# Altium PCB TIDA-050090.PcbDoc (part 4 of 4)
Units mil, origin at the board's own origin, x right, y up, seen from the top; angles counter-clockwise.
Board outline 4150 x 4140 mil, 8 copper layers (Top Layer 1, POWER1, GND1, SIGNAL1, SIGNAL2, GND2, POWER2, Bottom Layer 1), stack 60.703 mil thick; 130 components, 39 nets, 355 pads, 2292 vias.
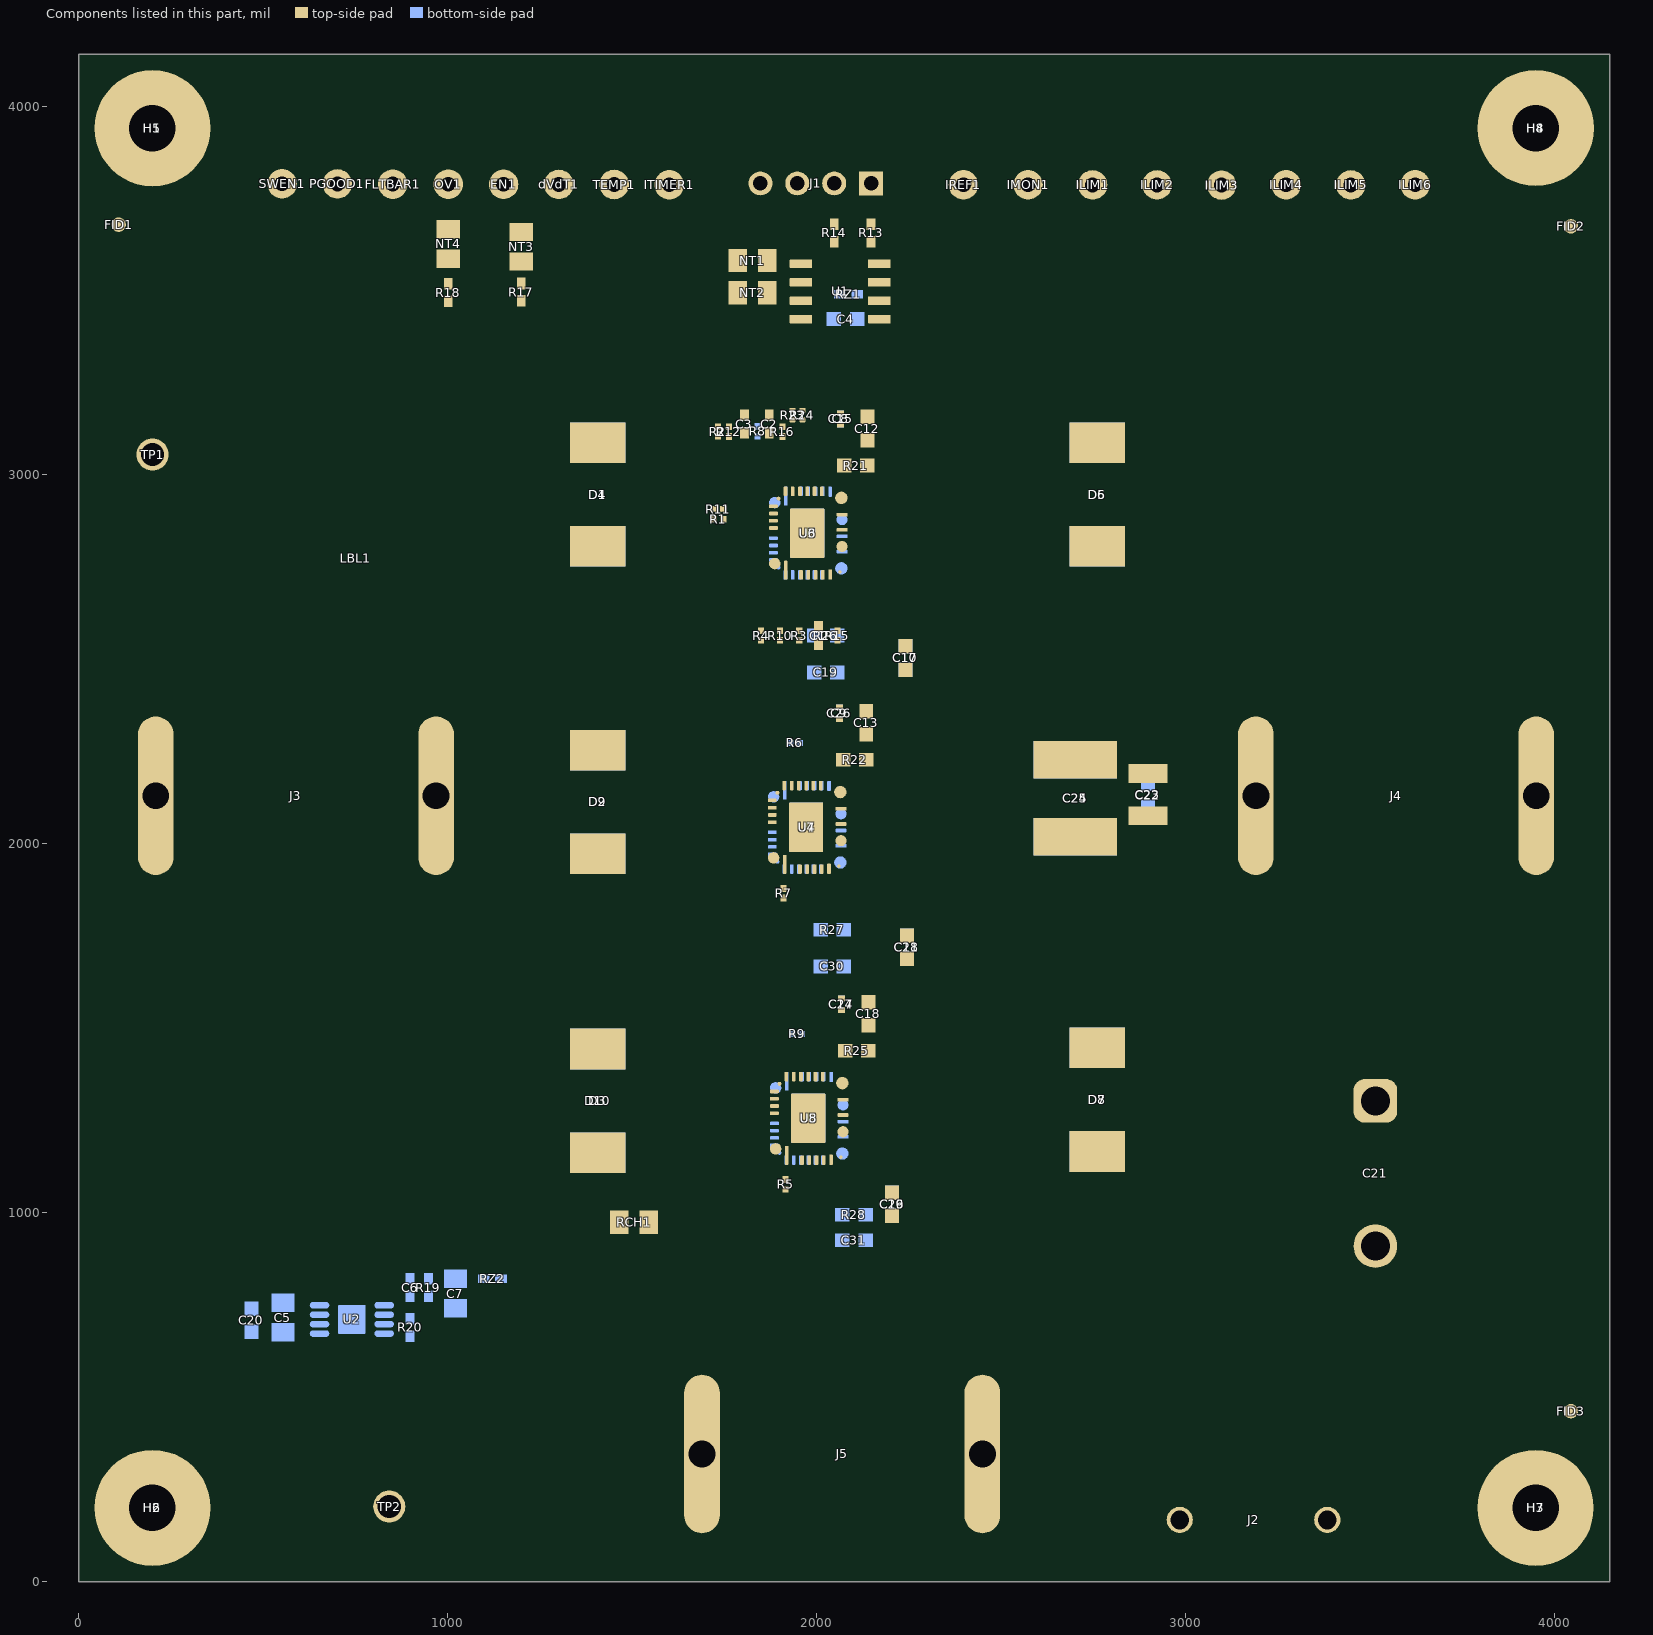
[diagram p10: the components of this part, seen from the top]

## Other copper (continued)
Bottom Layer 1:
  pour cut-out: 172.94,3678.58 ccw(c127.94,3678.58) 127.94,3723.58 ccw(c127.94,3678.58) 82.94,3678.58 ccw(c127.94,3678.58) 127.94,3633.58 ccw(c127.94,3678.58)
  pour cut-out: 4070.58,3674.15 ccw(c4025.58,3674.15) 4025.58,3719.15 ccw(c4025.58,3674.15) 3980.58,3674.15 ccw(c4025.58,3674.15) 4025.58,3629.15 ccw(c4025.58,3674.15)
  pour cut-out: 4090.27,482.52 ccw(c4045.27,482.52) 4045.27,527.52 ccw(c4045.27,482.52) 4000.27,482.52 ccw(c4045.27,482.52) 4045.27,437.52 ccw(c4045.27,482.52)
  region net QGND1: 2218.4,2492.36 2209.85,2483.81 2209.85,2428.49 2216.7,2421.65 2268.53,2421.65 2275.75,2428.87 2275.75,2485.14 2268.53,2492.36
  region net QGND1: 2222.34,1708.21 2213.79,1699.66 2213.79,1644.34 2220.64,1637.5 2272.47,1637.5 2279.69,1644.72 2279.69,1700.99 2272.47,1708.21
  region net PGND: 1486.21,3025.82 1328.73,3025.82 1318.89,3035.67 1318.89,3218.93 1342.31,3242.36 1476.37,3242.36 1496.05,3222.68 1496.05,3035.67
  region net PGND: 1486.21,2192.64 1328.73,2192.64 1318.89,2202.48 1318.89,2385.75 1342.31,2409.17 1476.37,2409.17 1496.05,2389.49 1496.05,2202.48
  region net PGND: 2840.3,3025.82 2682.82,3025.82 2672.97,3035.67 2672.97,3218.93 2696.4,3242.36 2830.45,3242.36 2850.14,3222.68 2850.14,3035.67
  region net PGND: 2682.8,1227.81 2840.28,1227.81 2850.13,1217.97 2850.13,1034.7 2826.7,1011.28 2692.65,1011.28 2672.96,1030.96 2672.96,1217.97
  region net PGND: 1318.89,948.42 1367.47,899.84 1481.58,899.84 1496.05,914.31 1496.05,1214.8 1486.21,1224.64 1328.73,1224.64 1318.89,1214.8
  region net PGND: 2603.36,2342.6 2603.36,2179.37 2639.36,2143.36 2947.85,2143.36 2951.82,2147.34 2951.82,2329.5 2921.02,2360.31 2621.07,2360.31
  region net PGND: 444.44,700.51 430.28,686.36 430.28,585.35 442.56,573.07 583.69,573.07 596.82,586.19 596.82,691.94 588.24,700.51
  region net PGND: 975.43,681.34 984.59,690.5 984.59,760.56 989.94,765.92 1060.29,765.92 1066.13,760.08 1066.13,602.6 1060.91,597.38 1023.75,597.38 839.95,597.38 796.92,640.41 729.34,640.41 698.94,670.81 698.94,754.71 702.93,758.7 778.74,758.7 784.45,753 784.45,698.51 801.62,681.34
  region net Efuse_OUT: 2682.82,2868.34 2840.3,2868.34 2850.14,2858.5 2850.14,2675.23 2826.71,2651.81 2692.66,2651.81 2672.97,2671.49 2672.97,2858.5
  region net Efuse_OUT: 2840.28,1385.3 2682.8,1385.3 2672.96,1395.14 2672.96,1578.41 2696.39,1601.83 2830.44,1601.83 2850.13,1582.15 2850.13,1395.14
  region net Efuse_OUT: 2121.52,2528.31 2135.82,2514.01 2196.23,2514.01 2196.43,2514.21 2392.29,2514.21 2392.49,2514.01 2411.41,2532.93 2411.41,2956.93 2391.72,2976.61 2201.03,2976.61 2138.22,2913.8 2052.94,2913.8 2050.25,2911.1 2050.24,2906.06 2050.24,2819.27 2059.85,2809.29 2091.74,2809.29 2121.52,2779.51
  region net Efuse_OUT: 2945.47,2121 2675.28,2121 2591.55,2037.27 2591.55,1902.38 2609.83,1884.09 2905.11,1884.09 2974.01,1952.99 2974.01,2092.47
  region net Efuse_OUT: 2170.34,1144.42 2170.34,1035.95 2178.5,1027.79 2404.18,1027.79 2414.02,1037.64 2414.02,1370.48 2394.34,1390.17 2203.65,1390.17 2140.84,1327.36 2055.56,1327.36 2052.86,1324.66 2052.86,1319.62 2052.86,1232.83 2062.47,1222.85 2091.92,1222.85
  region net Efuse_OUT: 2118.58,1730.81 2132.88,1716.51 2193.29,1716.51 2193.49,1716.71 2389.36,1716.71 2389.56,1716.51 2408.47,1735.43 2408.47,2159.43 2388.79,2179.11 2198.1,2179.11 2135.29,2116.3 2050.01,2116.3 2047.31,2113.6 2047.31,2108.56 2047.31,2021.77 2056.91,2011.79 2088.8,2011.79 2118.58,1982.01
  region net Efuse_OUT: 3163.01,2425.04 3131.61,2393.64 3131.61,1868.39 3157.95,1842.05 4033.05,1842.05 4045.18,1854.17 4045.18,2405.35 4025.49,2425.04
  region net Efuse_IN: 1328.73,2868.34 1486.21,2868.34 1496.05,2858.5 1496.05,2675.23 1472.63,2651.81 1338.57,2651.81 1318.89,2671.49 1318.89,2858.5
  region net Efuse_IN: 1328.73,2035.16 1486.21,2035.16 1496.05,2025.31 1496.05,1842.05 1472.63,1818.62 1338.57,1818.62 1318.89,1838.31 1318.89,2025.31
  region net Efuse_IN: 1486.21,1382.12 1328.73,1382.12 1318.89,1391.97 1318.89,1575.23 1342.31,1598.66 1476.37,1598.66 1496.05,1578.97 1496.05,1391.97
  region net Efuse_IN: 1784.51,2815.31 1784.51,2921.18 1793.67,2930.33 1834.41,2930.33 1847.4,2917.35 1847.4,2881.89 1858.25,2871.04 1889.26,2871.04 1903.15,2857.15 1903.15,2782.46 1914.68,2770.93 2019.34,2770.93 2022.6,2774.19 2022.6,2919.57 2007.15,2935.02 1945.58,2935.02 1930.71,2949.89 1930.71,2981.52 1908.02,3004.2 1714.97,3004.17 1692.9,2982.1 1692.9,2829.57 1651.04,2787.7 1651.04,2680.12 1670.92,2660.24 1836.45,2660.24 1843.18,2666.98 1843.18,2756.64
  region net Efuse_IN: 1958.04,1338.73 1933.32,1363.45 1933.32,1395.07 1910.64,1417.76 1717.59,1417.73 1705.36,1405.5 1705.36,1252.97 1653.65,1201.26 1653.65,1093.68 1673.53,1073.8 1839.06,1073.8 1845.8,1080.53 1845.8,1170.19 1796.6,1219.39 1796.6,1274.36 1806.84,1284.6 1891.87,1284.6 1905.76,1270.71 1905.76,1196.02 1917.3,1184.49 2021.95,1184.49 2025.22,1187.75 2025.22,1321.45 2007.93,1338.73
  region net Efuse_IN: 1952.49,2127.68 1927.77,2152.39 1927.77,2184.02 1905.09,2206.7 1712.04,2206.67 1699.81,2194.45 1699.81,2041.91 1648.1,1990.2 1648.1,1882.62 1667.98,1862.74 1833.51,1862.74 1840.25,1869.48 1840.25,1959.14 1791.05,2008.34 1791.05,2063.31 1801.28,2073.54 1886.32,2073.54 1900.21,2059.65 1900.21,1984.96 1911.74,1973.43 2016.4,1973.43 2019.67,1976.69 2019.66,2110.39 2002.38,2127.68
  region net Efuse_IN: 444.44,716.85 430.28,731.01 430.28,841.53 441.93,853.19 585.03,853.19 596.82,841.4 596.82,725.43 588.24,716.85
  region net Efuse_IN: 190.85,2419.05 155.94,2384.14 155.94,1882.95 196.84,1842.05 1050.86,1842.05 1062.98,1854.17 1062.98,2405.35 1049.29,2419.05
  text ".Layer_Name" at 572.49,-1004.76 h60

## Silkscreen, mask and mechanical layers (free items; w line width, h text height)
Top Overlay:
  lines w5: 1907.91,3149.76 1907.91,3208.74
  lines w10: 1702.76,935.04 1702.76,885.04 1739.97,885.04 ; 1702.76,981.2 1702.76,1018.41 ; 1702.76,1055.25 1702.76,1092.47 ; 1702.76,1129.3 1702.76,1166.52 ; 1702.76,1203.35 1702.76,1240.57 ; 1702.76,1277.4 1702.76,1314.62 ; 1702.76,1351.45 1702.76,1388.67 ; 1702.76,1425.5 1702.76,1462.72 ; 1702.76,1499.55 1702.76,1536.77 ; 1702.76,1573.6 1702.76,1610.82 ; 1702.76,1647.65 1702.76,1684.87 ; 1702.76,1721.7 1702.76,1758.92 ; 1702.76,1795.76 1702.76,1832.97 ; 1702.76,1869.81 1702.76,1907.02 ; 1702.76,1943.86 1702.76,1981.08 ; 1702.76,2017.91 1702.76,2055.13 ; 1702.76,2091.96 1702.76,2129.18 ; 1702.76,2166.01 1702.76,2203.23 ; 1702.76,2240.06 1702.76,2277.28 ; 1702.76,2314.11 1702.76,2351.33 ; 1702.76,2388.16 1702.76,2425.38 ; 1702.76,2462.21 1702.76,2499.43 ; 1702.76,2536.26 1702.76,2573.48 ; 1702.76,2610.31 1702.76,2647.53 ; 1702.76,2684.37 1702.76,2721.58 ; 1702.76,2758.42 1702.76,2832.47 ; 1702.76,2943.74 1702.76,3017.79 ; 1702.76,3054.62 1702.76,3091.84 ; 1702.76,3128.67 1702.76,3165.89 ; 1702.76,3202.72 1702.76,3276.77 1739.97,3276.77 ; 1776.81,885.04 1814.03,885.04 ; 1776.81,3276.77 1814.02,3276.77 ; 1850.86,885.04 1888.08,885.04 ; 1850.86,3276.77 1888.08,3276.77 ; 1924.91,885.04 1962.13,885.04 ; 1924.91,3276.77 1962.13,3276.77 ; 1998.96,885.04 2036.18,885.04 ; 1998.96,3276.77 2036.18,3276.77 ; 2073.01,885.04 2110.23,885.04 ; 2073.01,3276.77 2110.23,3276.77 ; 2147.06,885.04 2184.28,885.04 ; 2147.06,3276.77 2184.28,3276.77 ; 2221.11,885.04 2258.33,885.04 ; 2221.11,3276.77 2258.33,3276.77 ; 2295.16,885.04 2332.38,885.04 2332.38,935.04 ; 2295.16,3276.77 2332.38,3276.77 2332.38,3202.72 ; 2332.38,981.2 2332.38,1018.41 ; 2332.38,1055.25 2332.38,1092.47 ; 2332.38,1129.3 2332.38,1166.52 ; 2332.38,1203.35 2332.38,1240.57 ; 2332.38,1277.4 2332.38,1314.62 ; 2332.38,1351.45 2332.38,1388.67 ; 2332.38,1425.5 2332.38,1462.72 ; 2332.38,1499.55 2332.38,1536.77 ; 2332.38,1573.6 2332.38,1610.82 ; 2332.38,1647.65 2332.38,1684.87 ; 2332.38,1721.7 2332.38,1758.92 ; 2332.38,1795.76 2332.38,1832.97 ; 2332.38,1869.81 2332.38,1907.02 ; 2332.38,1943.86 2332.38,1981.08 ; 2332.38,2017.91 2332.38,2055.13 ; 2332.38,2091.96 2332.38,2129.18 ; 2332.38,2166.01 2332.38,2203.23 ; 2332.38,2240.06 2332.38,2277.28 ; 2332.38,2314.11 2332.38,2351.33 ; 2332.38,2388.16 2332.38,2425.38 ; 2332.38,2462.21 2332.38,2499.43 ; 2332.38,2536.26 2332.38,2573.48 ; 2332.38,2610.31 2332.38,2647.53 ; 2332.38,2684.37 2332.38,2721.58 ; 2332.38,2758.42 2332.38,2795.63 ; 2332.38,2832.47 2332.38,2869.68 ; 2332.38,2906.52 2332.38,2943.74 ; 2332.38,2980.57 2332.38,3017.79 ; 2332.38,3054.62 2332.38,3091.84 ; 2332.38,3128.67 2332.38,3165.89
  text "GND" at 1865.07,3877.28 h35 r90
  text "FLTB" at 1967.6,3877.28 h35 r90
  text "SCL" at 2061.35,3877.28 h35 r90
  text "SDA" at 2170.2,3873.11 h35 r90
  text "VIN" at 152.63,3158.78 h35
  text "Contact may cause burns" at 2635.42,2534.55 h100
  text "Do not touch!" at 2639.34,2441.43 h100
  text "TPS1689/5_5KW_Solution" at 119.1,1673.23 h60
  text "Contact may cause burns" at 107.22,1091.74 h100
  text "Do not touch!" at 108.27,986.4 h100
  text "PGND" at 782.55,320.19 h35
  text ".Layer_Name" at 572.49,-1004.76 h60
Bottom Overlay:
  drawing of 115 lines, arcs and shapes, not listed
  text "305-PD-24-0471" at 3675.41,367.65 h50
  text "AUG 2024" at 3645.02,280.09 h50
  text ".Layer_Name" at 572.49,-1004.76 h60
Top Paste:
  text ".Layer_Name" at 572.49,-1004.76 h60
Bottom Paste:
  text ".Layer_Name" at 572.49,-1004.76 h60
Top Solder:
  text ".Layer_Name" at 572.49,-1004.76 h60
  text ".Layer_Name" at 572.49,-1004.76 h60
Bottom Solder:
  text ".Layer_Name" at 572.49,-1004.76 h60
Drill Guide:
  text ".Layer_Name" at 572.49,-1004.76 h60
M1 Board Outline:
  the board outline again, w5
  text ".Layer_Name" at 493.75,-1004.76 h60
M2 Board Dimensions:
  rectangle: 120.49,-546.27 495.49,-421.27
  rectangle: -4.51,-421.27 120.49,-296.27
  lines w7: -4.51,-421.27 995.49,-421.27 ; 120.49,-546.27 120.49,-296.27 ; 245.49,-546.27 245.49,-296.27 ; 495.49,-546.27 495.49,-296.27 ; 745.49,-546.27 745.49,-296.27 ; -4.51,-546.27 -4.51,-296.27 995.49,-296.27 995.49,-546.27 -4.51,-546.27
  text ".Layer_Name" at 493.75,-1004.76 h60
M3 3D STEP Top:
  text ".Layer_Name" at 493.75,-1004.76 h60
M4 3D STEP Bottom:
  text ".Layer_Name" at 493.75,-1004.76 h60
M5 Assembly Top:
  lines w10: -316.19,-1076.43 5533.84,-1076.43 ; -316.19,-873.1 5533.84,-873.1 ; -316.19,-669.77 -316.19,-1279.77 3688.81,-1279.77 ; 1259.81,-1279.77 -315.69,-1279.77 -315.69,-669.77 5533.84,-669.77 5533.84,-1279.77 3212.43,-1279.77 ; 1967.7,-1279.77 1967.7,-669.77 ; 2998.48,-873.1 2998.48,-669.77 ; 3720.37,-873.1 3720.37,-669.77 ; 4224.26,-1286.27 4224.26,-1083.43
  text "COMPONENTS MARKED 'DNP' SHOULD NOT BE POPULATED." at 1026.94,-464.77 h60
  text "ASSEMBLY VARIANT:" at 1026.44,-580.27 h60
  text ".VariantName" at 2054.57,-580.27 h60
  text "PCB VIEWED FROM TOP SIDE" at -272.38,-801.93 h60
  text "BOARD #:" at 2011.21,-801.93 h60
  text ".PRJ_Number" at 2470.09,-801.93 h60
  text "REV:" at 3157.11,-801.93 h60
  text ".PCB_Rev" at 3389.56,-801.93 h60
  text "SVN REV:" at 3790.39,-801.93 h60
  text ".VersionControl_RevNumber" at 4284.58,-801.93 h60
  text "TID #:" at 2011.21,-1005.27 h60
  text ".TID" at 2470.09,-1005.27 h60
  text "GENERATED    :" at 2260.06,-1210.13 h60
  text ".Print_Date" at 2983.89,-1210.13 h60
  text ".Print_Time" at 3575.09,-1210.13 h60
  text "PLOT NAME =" at -272.38,-1210.6 h60
  text ".plot_File_Name" at 493.75,-1210.6 h60
  text "TEXAS INSTRUMENTS" at 4395.89,-1210.6 h60
M6 Assembly Bottom:
  lines w10: -316.69,-873.6 5533.84,-873.6 ; -314.69,-1076.93 5533.84,-1076.93 ; 1008.63,-1286.77 1008.63,-1083.93 ; 1551.89,-873.6 1551.89,-670.27 ; 2040.15,-1280.27 5533.84,-1280.27 4075.45,-1280.27 ; 2280.31,-1280.27 -316.69,-1280.27 -316.69,-670.27 5533.84,-670.27 ; 2293.46,-873.6 2293.46,-670.27 ; 3324.24,-1280.27 3324.24,-670.27 ; 5532.84,-1280.27 5532.84,-670.27 ; 5533.34,-1280.27 5533.34,-670.27
  text "COMPONENTS MARKED 'DNP' SHOULD NOT BE POPULATED." at 5699.85,-464.27 h60
  text ".VariantName" at 4360.58,-580.27 h60
  text "ASSEMBLY VARIANT:" at 5360.21,-580.27 h60
  text ".VersionControl_RevNumber" at 1030.99,-802.43 h60
  text "SVN REV:" at 1517.31,-802.43 h60
  text ".PCB_Rev" at 1922.07,-802.43 h60
  text "REV:" at 2162.39,-802.43 h60
  text ".PRJ_Number" at 2762.8,-802.43 h60
  text "BOARD #:" at 3229.56,-802.43 h60
  text "PCB VIEWED FROM BOTTOM SIDE" at 5489.52,-802.43 h60
  text ".TID" at 2782.48,-1005.77 h60
  text "TID #:" at 3229.56,-1005.77 h60
  text "TEXAS INSTRUMENTS" at 840.94,-1211.1 h60
  text ".Print_Time" at 2269.61,-1210.63 h60
  text ".Print_Date" at 2888.37,-1210.63 h60
  text "GENERATED    :" at 3671.26,-1210.63 h60
  text ".plot_File_Name" at 4821.82,-1211.1 h60
  text "PLOT NAME =" at 5489.52,-1211.1 h60
M9 Title Sheet:
  drawing of 54 lines, arcs and shapes, not listed
  text "1" at 656.33,11685.23 h70
  text "2" at 3014.34,11685.23 h70
  text "3" at 5390.99,11685.23 h70
  text "4" at 7766.34,11685.23 h70
  text "A" at -441.01,4295.23 h70
  text "A" at 8853.99,4295.23 h70
  text "B" at -441.01,2419.23 h70
  text "B" at 8853.99,2419.23 h70
  text "C" at -441.01,543.23 h70
  text "C" at 8853.99,543.23 h70
  text "PROJECT TITLE:" at 5818.99,-568.77 h45
  text "TPS1685_5KW_solution" at 5868.99,-702.09 h70
  text "DESIGNED FOR:" at 5818.99,-869.77 h45
  text ".Layer_Name" at 493.75,-1004.76 h60
  text ".PRJ_Customer" at 5868.99,-1009.77 h70
  text "FILE NAME:" at 5818.99,-1169.77 h45
  text ".PCB_File_Name_No_Path" at 5868.99,-1289.77 h50
  text "D" at -441.01,-1328.77 h70
  text "D" at 8853.99,-1328.77 h70
  text "Texas Instruments (TI) and/or its licensors do not warrant the accuracy or completeness of this specification" at 959.49,-1451.6 h45
  text "ENGINEER:" at 5818.99,-1459.77 h45
  text "LAYOUT BY:" at 7323.99,-1459.77 h45
  text "or any information contained therein. TI and/or its licensors do not warrant that this design will meet" at 914.51,-1564.27 h45
  text "Hamza, Hameem" at 5868.99,-1614.76 h70
  text ".PCB_Layout" at 7374.49,-1614.76 h70
  text "the specifications, will be suitable for your application or fit for any particular purpose, or will operate in" at 914.51,-1676.94 h45
  text "ALTIUM DESIGNER VERSION:" at 7323.99,-1769.77 h45
  text "an implementation. TI and/or its licensors do not warrant that the design is production worthy. You should" at 914.51,-1789.6 h45
  text "completely validate and test your design implementation to confirm the system functionality for your application." at 959.49,-1902.27 h40
  text ".print_Scale" at 5868.99,-1903.09 h70
  text ".Application_BuildNumber" at 7374.49,-1903.09 h70
  text "1" at 656.33,-2114.77 h70
  text "2" at 3014.34,-2114.77 h70
  text "3" at 5390.99,-2114.77 h70
  text "4" at 7766.34,-2114.77 h70
M10 Fab Notes:
  drawing of 189 lines, arcs and shapes, not listed
  text "FAB NOTE:" at -222.42,5968.83 h100
  text "1.NO VENDOR LOGO OR NAME ON THE BOARD" at -230.42,5773.44 h80
  text "2.ALL HOLES SHOULD BE FHS." at -230.42,5593.44 h80
  text "3.NEED TO REMOVE THE NON FUNCTIONAL PADS IN INNER LAYERS." at -230.42,5413.44 h80
  text "4.CLIP SILK ON NO MASK AREA." at -230.42,5241.1 h80
  text "5. ALL 7.87 MIL DRILLS SHOULD BE NON-CONDUCTIVE VIA PLUGGING FROM BOTH SIDE." at -230.42,5072.1 h80
  text "DESIGN INFORMATION" at 6855.01,5015.41 h60
  text "MIN. TRACK WIDTH:" at 6210.45,4883.28 h60
  text "10" at 7306.69,4883.29 h60
  text "MIL" at 7461.45,4883.28 h60
  text "6" at 7322.83,4763.78 h60
  text "MIN. CLEARANCE:" at 6210.45,4759.16 h60
  text "MIL" at 7461.45,4759.16 h60
  text "MIN. VIA PAD SIZE:" at 6210.45,4635.03 h60
  text "16" at 7276.7,4635.03 h60
  text "MIL" at 7461.45,4635.03 h60
  text "0.05mm (2MIL)" at 6905.45,4505.13 h60
  text "MINIMUM ANNULAR RING" at 5881.22,4496.91 h60
  text "EXTERNAL" at 7613.45,4496.91 h60
  text "PER" at 6081.22,4386.78 h60
  text "IPC-D-275 CLASS 2 LEVEL C" at 6301.22,4386.78 h60
  text "MIL, HOLES" at 7789.45,4286.3 h60
  text "+/-" at 7396.99,4277.72 h60
  text "+/-" at 8250.99,4277.72 h60
  text "REGISTRATION TOLERANCES:" at 5881.22,4276.65 h60
  text "METAL" at 7080.99,4276.65 h60
  text "5" at 7657.19,4276.66 h60
  text "3" at 8490.19,4276.66 h60
  text "MIL" at 8606.45,4276.65 h60
  text "HOLE SIZE TOLERANCE (UNLESS OTHERWISE SPECIFIED):" at 5881.22,4178.34 h60
  text "+/-" at 8250.99,4175.47 h60
  text "3" at 8490.19,4174.4 h60
  text "MIL" at 8606.45,4174.4 h60
  text "MATERIAL:" at 5806.45,4036.75 h60
  text "FR-4 High Tg" at 6792.89,3908.23 h60
  text "X" at 6648.46,3900.24 h60
  text "FR-4" at 6227.45,3895.72 h60
  text "OTHER" at 7715.45,3895.72 h60
  text "62 MIL (1.6mm) +/-10%" at 6547.55,3752.69 h60
  text "X" at 6427.46,3750.24 h60
  text "THICKNESS:" at 5881.22,3744.47 h60
  text "OTHER" at 7832.45,3744.47 h60
  text "TOLERANCE:" at 5881.22,3606.16 h60
  text "X" at 6729.46,3606.16 h60
  text "ANSI IPC-6012 TYPE 3 CLASS 2" at 6907.47,3606.16 h60
  text "OTHER +/-" at 6907.45,3461.97 h60
  text "BOW & TWIST:" at 5881.22,3316.78 h60
  text "X" at 6729.46,3316.78 h60
  text "ANSI IPC-6012 TYPE 3 CLASS 2" at 6907.47,3316.78 h60
  text "OTHER +/-" at 6907.45,3170.08 h60
  text "DRILLING:" at 5806.45,3039.46 h60
  text "NC_DRILL FILES" at 7567.45,2934.27 h60
  text "REFERENCE:" at 5881.22,2930.34 h60
  text "X" at 6538.46,2930.24 h60
  text "AS SHOWN" at 6716.45,2930.34 h60
  text "X" at 7439.46,2930.34 h60
  text "OTHER" at 7865.45,2788.09 h60
  text "PTH COPPER THICKNESS:" at 5880.9,2784.56 h60
  text "X" at 7020.13,2784.56 h60
  text "20-30 um" at 7148.13,2784.56 h60
  text "BOARD FINISH:" at 5806.45,2636.96 h60
  text "SILKSCREEN:" at 5961.67,2526.83 h60
  text "X" at 6919.46,2526.83 h60
  text "TOP" at 7036.45,2526.83 h60
  text "X" at 7429.46,2526.83 h60
  text "BOTTOM" at 7547.45,2526.83 h60
  text "SILKSCREEN COLOR:" at 5961.67,2371.64 h60
  text "X" at 6918.46,2371.64 h60
  text "WHITE" at 7036.45,2371.64 h60
  text "OTHER" at 7547.45,2371.64 h60
  text "X" at 7049.46,2228.2 h60
  text "GREEN" at 7167.45,2228.2 h60
  text "OTHER" at 7785.45,2228.2 h60
  text "SOLDER RESIST COLOR:" at 5961.67,2221.33 h60
  text "X" at 7049.46,2073.94 h60
  text "MATTE" at 7167.45,2073.94 h60
  text "SEMI-GLOSS" at 7784.99,2073.31 h60
  text "IMMERSION GOLD (ENIG)" at 6867.45,1901.17 h60
  text "ENEPIG" at 8204.99,1893.95 h60
  text "SURFACE FINISH:" at 5806.45,1892.95 h60
  text "X" at 6689.46,1892.95 h60
  text "IMM. TIN/SILVER OR EQUIV" at 6135.99,1755.64 h60
  text "OTHER" at 7567.45,1751.7 h60
  text "ARRAY/PANEL:" at 5806.45,1596.32 h60
  text "X" at 6689.46,1592.13 h60
  text "CUT AND TRIM PER M1 BOARD OUTLINE" at 6867.45,1588.1 h60
  text "N.C. ROUTE" at 6867.45,1452.13 h60
  text "V. SCORE" at 7733.45,1452.13 h60
  text "CERTIFICATION:" at 5806.45,1323.01 h60
  text "MATERIALS AND WORKMANSHIP FOR ALL PCBS" at 6531.45,1323.01 h60
  text "TO MEET OR EXCEED THE REQUIREMENTS OF:" at 6531.45,1228.94 h60
  text "X" at 6168.96,1100.31 h60
  text "ANSI IPC-A-600F CLASS ->" at 6296.95,1100.31 h60
  text "X" at 7944.96,1100.31 h60
  text "2" at 8054.95,1100.31 h60
  text "1" at 7739.95,1098.82 h60
  text "3" at 8408.95,1098.82 h60
  text "X" at 6980.96,952.63 h60
  text "RoHS" at 7108.95,952.63 h60
  text "OTHER" at 7753.36,952.63 h60
  text "PER ORDER" at 8150.41,952.63 h60
  text "ALL BOARDS MUST MEET OR EXCEED UL94-V0 REQUIREMENTS." at 5833.99,798.8 h60
  text "PCB MUST BEAR THE UL94V-0 UL REGISTERED MATERIAL ID NUMBER" at 5833.99,682.74 h60
  text "ADDITIONAL REQUIREMENTS:" at 5806.45,513.31 h60
  text "MICROSECTION:" at 5881.22,406.19 h60
  text "YES" at 6786.95,406.19 h60
  text "REQUIRED" at 7648.45,261.85 h60
  text "BARE BOARD ELEC. TEST:" at 5881.22,259 h60
  text "NONE" at 7186.95,259 h60
  text "X" at 7530.46,259 h60
  text "PER ORDER" at 8240.45,259 h60
  text "XX MIL VIAS REQUIRE NON-CONDUCTIVE FILL AND PLANARIZE" at 6049.37,54.05 h59
  text "XX MIL VIAS REQUIRE CONDUCTIVE FILL AND PLANARIZE" at 6057.37,-49.92 h60
  text "OUTER XX MIL TRACES REQUIRE 50 OHM SINGLE-ENDED IMPEDANCE" at 6056.38,-213.31 h58
  text "LAYER 2 & 3 (INNER LAYERS) XX MIL WIDE, XX MIL SPACE / TRACES REQUIRE 100 OHM DIFFERENTIAL IMPEDANCE" at 6048.38,-449.02 h60
  text ".Layer_Name" at 493.75,-1004.76 h60
M11 Gerber Information:
  circle w10: c4150,-261.62 r30
  circle w10: c4150,-261.62 r60
  circle w10: c4150,4573.03 r30
  circle w10: c4150,4573.03 r60
  circle w10: c0,4573.03 r60
  circle w10: c0,4573.03 r30
  lines w10: -316.19,-1076.43 5533.84,-1076.43 ; -316.19,-873.1 5533.84,-873.1 ; -316.19,-669.77 -316.19,-1279.77 3688.81,-1279.77 ; -83.5,4573.03 83.5,4573.03 ; 0,4498.03 0,4648.03 ; 1259.81,-1279.77 -315.69,-1279.77 -315.69,-669.77 5533.84,-669.77 5533.84,-1279.77 3212.43,-1279.77 ; 1680.61,-873.1 1680.61,-669.77 ; 1967.7,-1076.43 1967.7,-873.1 ; 2608.82,-1279.77 2608.82,-1076.43 ; 3369.1,-873.1 3369.1,-669.77 ; 3720.37,-873.1 3720.37,-669.77 ; 4066.5,-261.62 4233.5,-261.62 ; 4066.5,4573.03 4233.5,4573.03 ; 4150,-336.62 4150,-186.62 ; 4150,4498.03 4150,4648.03 ; 4479.92,-1286.27 4479.92,-1076.43
  text "ALL ARTWORK VIEWED FROM TOP SIDE" at -272.38,-801.93 h60
  text "BOARD #:" at 1715.93,-801.93 h60
  text "TPS1685_5KW_solution" at 2174.82,-801.93 h60
  text "REV:" at 3404.02,-801.93 h60
  text "A" at 3636.46,-801.93 h60
  text "SVN REV:" at 3790.39,-801.93 h60
  text ".VersionControl_RevNumber" at 4284.58,-801.93 h60
  text "LAYER NAME =" at -272.38,-1004.76 h60
  text "TID #:" at 2011.21,-1005.27 h60
  text ".TID" at 2470.09,-1005.27 h60
  text ".plot_File_Name" at 413.39,-1190.94 h35
  text "GENERATED:" at 2640.89,-1210.13 h60
  text ".Print_Date" at 3239.55,-1210.13 h60
  text ".Print_Time" at 3830.75,-1210.13 h60
  text "PLOT NAME =" at -272.38,-1210.6 h60
  text "TEXAS INSTRUMENTS" at 4507.87,-1210.63 h60
M12 Stackup:
  lines w10: 3520.77,9249.89 3682.66,9249.89 ; 3520.77,9489.89 3682.66,9489.89 ; 3520.77,9729.89 3682.66,9729.89 ; 3520.77,9969.89 3682.66,9969.89 ; 3520.77,10209.89 3682.66,10209.89 ; 3520.77,10449.89 3682.66,10449.89 ; 3520.77,10689.89 3682.66,10689.89 ; 3520.77,10929.89 3682.66,10929.89 ; 3638.66,9293.89 3682.66,9249.89 ; 3638.66,9533.89 3682.66,9489.89 ; 3638.66,9773.89 3682.66,9729.89 ; 3638.66,10013.89 3682.66,9969.89 ; 3638.66,10253.89 3682.66,10209.89 ; 3638.66,10493.89 3682.66,10449.89 ; 3638.66,10733.89 3682.66,10689.89 ; 3638.66,10973.89 3682.66,10929.89 ; 3639.66,9206.89 3682.66,9249.89 ; 3639.66,9446.89 3682.66,9489.89 ; 3639.66,9686.89 3682.66,9729.89 ; 3639.66,9926.89 3682.66,9969.89 ; 3639.66,10166.89 3682.66,10209.89 ; 3639.66,10406.89 3682.66,10449.89 ; 3639.66,10646.89 3682.66,10689.89 ; 3639.66,10886.89 3682.66,10929.89
  lines w15: 77.66,9061.81 487.57,9061.81 1417.31,9061.81 2277.08,9061.81 2926.92,9061.81 3496.78,9061.81 ; 77.66,9181.81 487.57,9181.81 1417.31,9181.81 2277.08,9181.81 2926.92,9181.81 3496.78,9181.81 ; 77.66,9301.81 487.57,9301.81 1417.31,9301.81 2277.08,9301.81 2926.92,9301.81 3496.78,9301.81 ; 77.66,9421.81 487.57,9421.81 1417.31,9421.81 2277.08,9421.81 2926.92,9421.81 3496.78,9421.81 ; 77.66,9541.81 487.57,9541.81 1417.31,9541.81 2277.08,9541.81 2926.92,9541.81 3496.78,9541.81 ; 77.66,9661.81 487.57,9661.81 1417.31,9661.81 2277.08,9661.81 2926.92,9661.81 3496.78,9661.81 ; 77.66,9781.81 487.57,9781.81 1417.31,9781.81 2277.08,9781.81 2926.92,9781.81 3496.78,9781.81 ; 77.66,9901.81 487.57,9901.81 1417.31,9901.81 2277.08,9901.81 2926.92,9901.81 3496.78,9901.81 ; 77.66,10021.81 487.57,10021.81 1417.31,10021.81 2277.08,10021.81 2926.92,10021.81 3496.78,10021.81 ; 77.66,10141.81 487.57,10141.81 1417.31,10141.81 2277.08,10141.81 2926.92,10141.81 3496.78,10141.81 ; 77.66,10261.81 487.57,10261.81 1417.31,10261.81 2277.08,10261.81 2926.92,10261.81 3496.78,10261.81 ; 77.66,10381.81 487.57,10381.81 1417.31,10381.81 2277.08,10381.81 2926.92,10381.81 3496.78,10381.81 ; 77.66,10501.81 487.57,10501.81 1417.31,10501.81 2277.08,10501.81 2926.92,10501.81 3496.78,10501.81 ; 77.66,10621.81 487.57,10621.81 1417.31,10621.81 2277.08,10621.81 2926.92,10621.81 3496.78,10621.81 ; 77.66,10741.81 487.57,10741.81 1417.31,10741.81 2277.08,10741.81 2926.92,10741.81 3496.78,10741.81 ; 77.66,10861.81 487.57,10861.81 1417.31,10861.81 2277.08,10861.81 2926.92,10861.81 3496.78,10861.81 ; 77.66,10981.81 487.57,10981.81 1417.31,10981.81 2277.08,10981.81 2926.92,10981.81 3496.78,10981.81 ; 77.66,11101.81 487.57,11101.81 1417.31,11101.81 2277.08,11101.81 2926.92,11101.81 3496.78,11101.81 ; 77.66,11221.81 3496.78,11221.81 ; 487.57,11341.81 487.57,8941.81 ; 1417.31,11341.81 1417.31,8941.81 ; 2277.08,11341.81 2277.08,8941.81 ; 2926.92,11341.81 2926.92,8941.81 ; 487.57,8941.81 1417.31,8941.81 ; 487.57,8941.81 77.66,8941.81 77.66,11341.81 3496.78,11341.81 3496.78,8941.81 2926.92,8941.81 ; 1417.31,8941.81 2277.08,8941.81 ; 2277.08,8941.81 2926.92,8941.81
  text "STACKUP DETAIL:" at 58.17,11393.07 h60
  text "Layer" at 147.66,11251.81 h60
  text "Name" at 557.57,11251.81 h60
  text "Material" at 1487.31,11251.81 h60
  text "Thickness" at 2347.08,11251.81 h60
  text "Constant" at 2996.92,11251.81 h60
  text "Top Overlay" at 557.57,11131.81 h60
  text "Top Solder" at 557.57,11011.81 h60
  text "Solder Resist" at 1487.31,11011.81 h60
  text "1.00mil" at 2347.08,11011.81 h60
  text "3.5" at 2996.92,11011.81 h60
  text "2 Oz (1.5 Oz + Plating)" at 3712.66,10912.69 h50
  text "1" at 147.66,10891.81 h60
  text "Top Layer 1" at 557.57,10891.81 h60
  text "Copper" at 1487.31,10891.81 h60
  text "2.76mil" at 2347.08,10891.81 h60
  text "Dielectric 1" at 557.57,10771.81 h60
  text "FR-4 High Tg" at 1487.31,10771.81 h60
  text "5.42mil" at 2347.08,10771.81 h60
  text "4.1" at 2996.92,10771.81 h60
  text "1 Oz" at 3712.66,10672.69 h50
  text "2" at 147.66,10651.81 h60
  text "POWER1" at 557.57,10651.81 h60
  text "Copper" at 1487.31,10651.81 h60
  text "1.26mil" at 2347.08,10651.81 h60
  text "Dielectric 2" at 557.57,10531.81 h60
  text "FR-4 High Tg" at 1487.31,10531.81 h60
  text "8.00mil" at 2347.08,10531.81 h60
  text "4.1" at 2996.92,10531.81 h60
  text "1 Oz" at 3712.66,10432.69 h50
  text "3" at 147.66,10411.81 h60
  text "GND1" at 557.57,10411.81 h60
  text "Copper" at 1487.31,10411.81 h60
  text "1.26mil" at 2347.08,10411.81 h60
  text "Dielectric 3" at 557.57,10291.81 h60
  text "FR-4 High Tg" at 1487.31,10291.81 h60
  text "6.40mil" at 2347.08,10291.81 h60
  text "4.1" at 2996.92,10291.81 h60
  text "1 Oz" at 3712.66,10192.69 h50
  text "4" at 147.66,10171.81 h60
  text "SIGNAL1" at 557.57,10171.81 h60
  text "Copper" at 1487.31,10171.81 h60
  text "1.26mil" at 2347.08,10171.81 h60
  text "Dielectric 4" at 557.57,10051.81 h60
  text "FR-4 High Tg" at 1487.31,10051.81 h60
  text "8.00mil" at 2347.08,10051.81 h60
  text "4.8" at 2996.92,10051.81 h60
  text "1 Oz" at 3712.66,9952.69 h50
  text "5" at 147.66,9931.81 h60
  text "SIGNAL2" at 557.57,9931.81 h60
  text "Copper" at 1487.31,9931.81 h60
  text "1.26mil" at 2347.08,9931.81 h60
  text "Dielectric 5" at 557.57,9811.81 h60
  text "FR-4 High Tg" at 1487.31,9811.81 h60
  text "6.40mil" at 2347.08,9811.81 h60
  text "4.1" at 2996.92,9811.81 h60
  text "1 Oz" at 3712.66,9712.69 h50
  text "6" at 147.66,9691.81 h60
  text "GND2" at 557.57,9691.81 h60
  text "Copper" at 1487.31,9691.81 h60
  text "1.26mil" at 2347.08,9691.81 h60
  text "Dielectric 6" at 557.57,9571.81 h60
  text "FR-4 High Tg" at 1487.31,9571.81 h60
  text "8.00mil" at 2347.08,9571.81 h60
  text "4.1" at 2996.92,9571.81 h60
  text "1 Oz" at 3712.66,9472.69 h50
  text "7" at 147.66,9451.81 h60
  text "POWER2" at 557.57,9451.81 h60
  text "Copper" at 1487.31,9451.81 h60
  text "1.26mil" at 2347.08,9451.81 h60
  text "Dielectric 7" at 557.57,9331.81 h60
  text "FR-4 High Tg" at 1487.31,9331.81 h60
  text "5.42mil" at 2347.08,9331.81 h60
  text "4.1" at 2996.92,9331.81 h60
  text "2 Oz (1.5 Oz + Plating)" at 3712.66,9232.69 h50
  text "8" at 147.66,9211.81 h60
  text "Bottom Layer 1" at 557.57,9211.81 h60
  text "Copper" at 1487.31,9211.81 h60
  text "2.76mil" at 2347.08,9211.81 h60
  text "Bottom Solder" at 557.57,9091.81 h60
  text "Solder Resist" at 1487.31,9091.81 h60
  text "1.00mil" at 2347.08,9091.81 h60
  text "3.5" at 2996.92,9091.81 h60
  text "Bottom Overlay" at 557.57,8971.81 h60
  text "Total board thickness:" at 147.66,8851.81 h60
  text "62.70mil" at 2347.08,8851.81 h60
  text ".Layer_Name" at 493.75,-1004.76 h60
M13 Component Bodies Top:
  text ".Layer_Name" at 493.75,-1004.76 h60
M14 Component Bodies Bottom:
  text ".Layer_Name" at 493.75,-1004.76 h60
M15 Courtyards Top:
  text ".Layer_Name" at 493.75,-1004.76 h60
M16 Courtyards Bottom:
  text ".Layer_Name" at 493.75,-1004.76 h60
Drill Drawing:
  circle w10: c-178.16,8057.51 r33.33
  circle w10: c-178.16,7757.51 r20
  circle w10: c-178.16,7757.51 r33.33
  lines w10: -211.5,6707.51 -178.16,6674.17 -144.83,6707.51 -178.16,6740.84 -211.5,6707.51 ; -211.5,6824.17 -211.5,6840.84 -194.83,6857.51 -211.5,6874.17 -211.5,6890.84 -194.83,6890.84 -178.16,6874.17 -161.5,6890.84 -144.83,6890.84 -144.83,6874.17 -161.5,6857.51 -144.83,6840.84 -144.83,6824.17 -161.5,6824.17 -178.16,6840.84 -194.83,6824.17 -211.5,6824.17 ; -211.5,6990.84 -194.83,6990.84 -194.83,6974.17 -161.5,6974.17 -161.5,6990.84 -144.83,6990.84 -144.83,7024.17 -161.5,7024.17 -161.5,7040.84 -194.83,7040.84 -194.83,7024.17 -211.5,7024.17 -211.5,6990.84 ; -211.5,7124.17 -178.16,7140.84 -144.83,7124.17 -161.5,7157.51 -144.83,7190.84 -178.16,7174.17 -211.5,7190.84 -194.83,7157.51 -211.5,7124.17 ; -211.5,7274.17 -144.83,7274.17 -144.83,7340.84 -211.5,7340.84 -211.5,7274.17 ; -211.5,7440.84 -194.83,7440.84 -178.16,7424.17 -161.5,7440.84 -144.83,7440.84 -161.5,7457.51 -144.83,7474.17 -161.5,7474.17 -178.16,7490.84 -194.83,7474.17 -211.5,7474.17 -194.83,7457.51 -211.5,7440.84 ; -211.5,7640.84 -144.83,7640.84 -178.16,7574.17 -211.5,7640.84 ; -211.5,7890.84 -194.83,7890.84 -178.16,7874.17 -161.5,7890.84 -144.83,7890.84 -161.5,7907.51 -144.83,7924.17 -161.5,7924.17 -178.16,7940.84 -194.83,7924.17 -211.5,7924.17 -194.83,7907.51 -211.5,7890.84 ; -211.5,8240.84 -144.83,8240.84 -178.16,8174.17 -211.5,8240.84 ; -198.16,7287.51 -158.16,7287.51 -158.16,7327.51 -198.16,7327.51 -198.16,7287.51 ; -198.16,7447.51 -188.16,7447.51 -178.16,7437.51 -168.16,7447.51 -158.16,7447.51 -168.16,7457.51 -158.16,7467.51 -168.16,7467.51 -178.16,7477.51 -188.16,7467.51 -198.16,7467.51 -188.16,7457.51 -198.16,7447.51 ; -198.16,8227.51 -158.16,8227.51 -178.16,8187.51 -198.16,8227.51
  lines w15: -271.29,6629.17 8732.17,6629.17 ; -271.29,8279.17 8732.17,8279.17 ; 279.59,6479.17 279.59,8429.17 ; 939.41,6479.17 939.41,8429.17 ; 2089.07,6479.17 2089.07,8429.17 ; 2594.95,6479.17 2594.95,8429.17 ; 3328.75,6479.17 3328.75,8429.17 ; 5048.23,6479.17 5048.23,8429.17 ; 6129.92,6479.17 6129.92,8429.17 ; 7487.52,6479.17 7487.52,8429.17 ; -271.29,6479.17 8732.17,6479.17 8732.17,8429.17 -271.29,8429.17 -271.29,6479.17
  text "DRILL TABLE:" at -271.29,8503.94 h80
  text "Symbol" at -181.29,8324.17 h72
  text "Count" at 324.59,8324.17 h72
  text "Hole Size" at 984.41,8324.17 h72
  text "Plated" at 2134.07,8324.17 h72
  text "Hole Type" at 2639.95,8324.17 h72
  text "Drill Layer Pair" at 3373.75,8324.17 h72
  text "Hole Tolerance" at 5093.23,8324.17 h72
  text "Routed Path Length" at 6174.92,8324.17 h72
  text "Hole Length" at 7532.52,8324.17 h72
  text "2" at 324.59,8174.17 h60
  text "51.18mil (1.300mm)" at 984.41,8174.17 h60
  text "PTH" at 2134.07,8174.17 h60
  text "Round" at 2639.95,8174.17 h60
  text "Top Layer 1 - Bottom Layer 1" at 3373.75,8174.17 h60
  text "+3/-3 mil" at 5093.23,8174.17 h60
  text "-" at 6174.92,8174.17 h60
  text "-" at 7532.52,8174.17 h60
  text "2" at 324.59,8024.17 h60
  text "63.00mil (1.600mm)" at 984.41,8024.17 h60
  text "PTH" at 2134.07,8024.17 h60
  text "Round" at 2639.95,8024.17 h60
  text "Top Layer 1 - Bottom Layer 1" at 3373.75,8024.17 h60
  text "+3/-3 mil" at 5093.23,8024.17 h60
  text "-" at 6174.92,8024.17 h60
  text "-" at 7532.52,8024.17 h60
  text "2" at 324.59,7874.17 h60
  text "78.74mil (2.000mm)" at 984.41,7874.17 h60
  text "PTH" at 2134.07,7874.17 h60
  text "Round" at 2639.95,7874.17 h60
  text "Top Layer 1 - Bottom Layer 1" at 3373.75,7874.17 h60
  text "+3/-3 mil" at 5093.23,7874.17 h60
  text "-" at 6174.92,7874.17 h60
  text "-" at 7532.52,7874.17 h60
  text "4" at 324.59,7724.17 h60
  text "39.37mil (1.000mm)" at 984.41,7724.17 h60
  text "PTH" at 2134.07,7724.17 h60
  text "Round" at 2639.95,7724.17 h60
  text "Top Layer 1 - Bottom Layer 1" at 3373.75,7724.17 h60
  text "+3/-3 mil" at 5093.23,7724.17 h60
  text "-" at 6174.92,7724.17 h60
  text "-" at 7532.52,7724.17 h60
  text "4" at 324.59,7574.17 h60
  text "125.98mil (3.200mm)" at 984.41,7574.17 h60
  text "NPTH" at 2134.07,7574.17 h60
  text "Round" at 2639.95,7574.17 h60
  text "Top Layer 1 - Bottom Layer 1" at 3373.75,7574.17 h60
  text "+2/-2 mil" at 5093.23,7574.17 h60
  text "-" at 6174.92,7574.17 h60
  text "-" at 7532.52,7574.17 h60
  text "6" at 324.59,7424.17 h60
  text "72.99mil (1.854mm)" at 984.41,7424.17 h60
  text "PTH" at 2134.07,7424.17 h60
  text "Slot" at 2639.95,7424.17 h60
  text "Top Layer 1 - Bottom Layer 1" at 3373.75,7424.17 h60
  text "+3/-3 mil" at 5093.23,7424.17 h60
  text "327.01mil (8.306mm)" at 6174.92,7424.17 h60
  text "400.00mil (10.160mm)" at 7532.52,7424.17 h60
  text "16" at 324.59,7274.17 h60
  text "40.00mil (1.016mm)" at 984.41,7274.17 h60
  text "PTH" at 2134.07,7274.17 h60
  text "Round" at 2639.95,7274.17 h60
  text "Top Layer 1 - Bottom Layer 1" at 3373.75,7274.17 h60
  text "+3/-3 mil" at 5093.23,7274.17 h60
  text "-" at 6174.92,7274.17 h60
  text "-" at 7532.52,7274.17 h60
  text "41" at 324.59,7124.17 h60
  text "7.87mil (0.200mm)" at 984.41,7124.17 h60
  text "PTH" at 2134.07,7124.17 h60
  text "Round" at 2639.95,7124.17 h60
  text "Top Layer 1 - Bottom Layer 1" at 3373.75,7124.17 h60
  text "+3/-3 mil" at 5093.23,7124.17 h60
  text "-" at 6174.92,7124.17 h60
  text "-" at 7532.52,7124.17 h60
  text "67" at 324.59,6974.17 h60
  text "8.00mil (0.203mm)" at 984.41,6974.17 h60
  text "PTH" at 2134.07,6974.17 h60
  text "Round" at 2639.95,6974.17 h60
  text "Top Layer 1 - Bottom Layer 1" at 3373.75,6974.17 h60
  text "+3/-3 mil" at 5093.23,6974.17 h60
  text "-" at 6174.92,6974.17 h60
  text "-" at 7532.52,6974.17 h60
  text "444" at 324.59,6824.17 h60
  text "10.00mil (0.254mm)" at 984.41,6824.17 h60
  text "PTH" at 2134.07,6824.17 h60
  text "Round" at 2639.95,6824.17 h60
  text "Top Layer 1 - Bottom Layer 1" at 3373.75,6824.17 h60
  text "+3/-3 mil" at 5093.23,6824.17 h60
  text "-" at 6174.92,6824.17 h60
  text "-" at 7532.52,6824.17 h60
  text "1740" at 324.59,6674.17 h60
  text "12.00mil (0.305mm)" at 984.41,6674.17 h60
  text "PTH" at 2134.07,6674.17 h60
  text "Round" at 2639.95,6674.17 h60
  text "Top Layer 1 - Bottom Layer 1" at 3373.75,6674.17 h60
  text "+3/-3 mil" at 5093.23,6674.17 h60
  text "-" at 6174.92,6674.17 h60
  text "-" at 7532.52,6674.17 h60
  text "2328 Total" at 324.59,6524.17 h60
  text "Slot definitions :" at -181.29,6379.2 h60
  text "Routed Path Length" at 851.4,6379.2 h60
  text "= Calculated from tool start centre position to tool end centre position." at 1954.07,6379.2 h60
  text "Hole Length" at 851.4,6279.23 h60
  text "= Routed Path Length + Tool Size = Slot length as defined in the PCB layout" at 1544.2,6279.23 h60
  text ".Layer_Name" at 493.75,-1004.76 h60
M17 Embedded Cavity:
  text ".Layer_Name" at 493.75,-1004.76 h60
M18 Embedded Assembly:
  text ".Layer_Name" at 493.75,-1004.76 h60
M19 Embedded Keepout:
  text ".Layer_Name" at 497.69,-1008.7 h60

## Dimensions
0,4140 to 4150,4140 on M2 Board Dimensions
0,4140 to 0,0 on M2 Board Dimensions
-4.51,-546.27 to 995.49,-546.27 on M2 Board Dimensions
